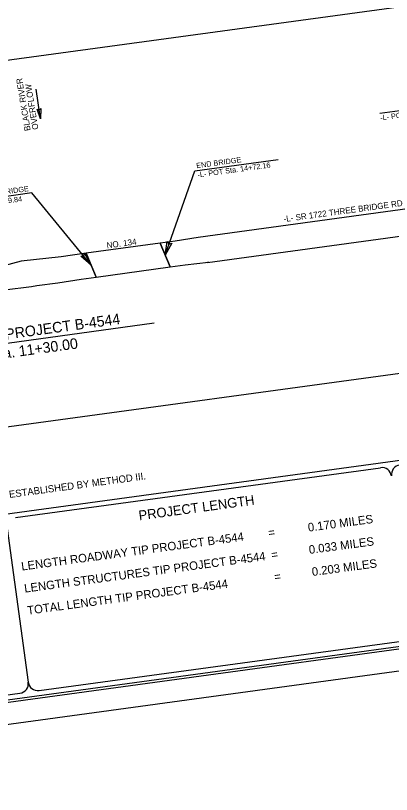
# Model space of a CAD drawing. Extents: x 2110583 to 2112764, y 580993 to 582575.
# Drawn here: x 2111407 to 2111873, y 580993 to 581957 of the extents above; entities that cross this region are included whole.
import ezdxf

# ---------------------------------------------------------------- set-up
doc = ezdxf.new("R2010")
doc.units = 0
for name, color, linetype in [('Default', 7, 'Continuous'), ('Prop DSN Text', 7, 'Continuous'), ('Prop Horizontal Alignment Station Label', 7, 'Continuous'), ('Prop Roadway Bridge', 7, 'Continuous'), ('Prop Shade Medium', 7, 'Continuous'), ('Prop Terminator CELL', 7, 'Continuous'), ('Sheet Data Field CELL', 7, 'Continuous'), ('Sheet Plot Border Inside CELL', 7, 'Continuous'), ('Sheet Plot Border Outside CELL', 7, 'Continuous'), ('Sheet Title CELL', 7, 'Continuous')]:
    doc.layers.add(name, color=color, linetype=linetype)

msp = doc.modelspace()

# ---------------------------------------------------------------- linework, layer by layer
at = {"layer": 'Default'}
msp.add_lwpolyline([(2111026.43, 581851.1), (2112527.69, 582055.98), (2112588.53, 581610.11), (2111087.27, 581405.24)], close=True, dxfattribs=at)
at = {"layer": 'Prop DSN Text'}
msp.add_line((2111437.98, 581828.89), (2111432.93, 581865.9), dxfattribs=at)
at = {"layer": 'Prop Horizontal Alignment Station Label'}
for p, q in [((2111962.26, 581849.66), (2111858.44, 581835.48)), ((2111629.48, 581764.81), (2111732.27, 581778.85)), ((2111592.36, 581660.37), (2111629.48, 581764.81)), ((2111427.45, 581737.24), (2111323.42, 581723.03)), ((2111500.89, 581647.89), (2111427.45, 581737.24)), ((2111579.06, 581576.04), (2111302.47, 581538.26))]:
    msp.add_line(p, q, dxfattribs=at)
at = {"layer": 'Prop Roadway Bridge'}
for p, q in [((2111586.18, 581675.09), (2111494.71, 581662.61)), ((2111598.54, 581645.66), (2111586.18, 581675.09)), ((2111494.71, 581662.61), (2111507.07, 581633.17)), ((2111507.07, 581633.17), (2111598.54, 581645.66))]:
    msp.add_line(p, q, dxfattribs=at)
at = {"layer": 'Prop Shade Medium'}
for p, q in [((2111994.42, 581731.39), (2111633.58, 581682.15)), ((2111644.95, 581651.4), (2111998.75, 581699.68)), ((2111604.76, 581677.63), (2111586.18, 581675.09)), ((2111586.18, 581675.09), (2111598.54, 581645.66)), ((2111633.58, 581682.15), (2111604.76, 581677.63)), ((2111463.75, 581658.38), (2111414.17, 581652.66)), ((2111494.71, 581662.61), (2111463.75, 581658.38)), ((2111507.07, 581633.17), (2111494.71, 581662.61)), ((2111414.17, 581652.66), (2111387.83, 581645.97)), ((2111598.54, 581645.66), (2111617.12, 581648.19)), ((2111617.12, 581648.19), (2111646.1, 581651.56)), ((2111646.1, 581651.56), (2111644.95, 581651.4)), ((2111459.66, 581626.12), (2111488.49, 581630.64)), ((2111488.49, 581630.64), (2111507.17, 581633.19)), ((2111433.71, 581622.58), (2111459.66, 581626.12))]:
    msp.add_line(p, q, dxfattribs=at)
msp.add_arc((2111114.87, 583958.95), 2358.03, 275.14998, 277.77101, dxfattribs=at)
at = {"layer": 'Prop Terminator CELL'}
for points in [[(2111438.43, 581841.67), (2111437.98, 581828.89), (2111434.05, 581841.15), (2111436.49, 581839.85)], [(2111600.6, 581675.04), (2111592.36, 581660.37), (2111595.17, 581677.07), (2111597.24, 581674.09)], [(2111492.57, 581662.51), (2111500.89, 581647.89), (2111488.02, 581658.9), (2111491.65, 581659.14)]]:
    msp.add_lwpolyline(points, close=True, dxfattribs=at)
at = {"layer": 'Sheet Plot Border Inside CELL'}
msp.add_lwpolyline([(2110773, 581021.72), (2112754.79, 581292.17), (2112583.51, 582547.28), (2110601.71, 582276.83)], close=True, dxfattribs=at)
at = {"layer": 'Sheet Plot Border Outside CELL'}
msp.add_lwpolyline([(2112585.22, 582574.72), (2110582.61, 582301.43), (2110761.18, 580992.92), (2112763.78, 581266.21)], close=True, dxfattribs=at)
at = {"layer": 'Sheet Title CELL'}
for p, q in [((2111002.17, 581286.33), (2112690.83, 581516.78)), ((2111407.31, 581335.54), (2111859.2, 581397.21)), ((2111397.04, 581322.04), (2111423.01, 581131.71))]:
    msp.add_line(p, q, dxfattribs=at)
for points in [[(2110967.61, 581051.37), (2112727.62, 581291.56)], [(2111436.53, 581121.42), (2111888.43, 581183.09)], [(2111240.31, 581094.66), (2111412.74, 581118.19)]]:
    msp.add_lwpolyline(points, dxfattribs=at)
for centre, major_axis, start_param, end_param in [((2111860.82, 581385.39), (-1.62, 11.9), 4.712389, 6.283185), ((2111884.61, 581388.63), (-1.62, 11.9), 0, 1.570796), ((2111411.12, 581130.14), (1.62, -11.9), 0, 1.570796), ((2111434.9, 581133.39), (1.62, -11.9), 4.712389, 6.283185)]:
    msp.add_ellipse(centre, major_axis=major_axis, ratio=0.999692, start_param=start_param, end_param=end_param, dxfattribs=at)

# ---------------------------------------------------------------- texts
at = {"layer": 'Prop DSN Text'}
for s, height, rotation, p in [('BLACK RIVER', 7.4721, 99.25807, (2111425.98, 581814.64)), ('OVERFLOW', 7.472, 99.25807, (2111435.65, 581816.22)), ('-L- SR 1722 THREE BRIDGE RD ', 7.4721, 7.77101, (2111739.6, 581701.16)), ('NO. 134', 7.472, 7.49037, (2111520.56, 581668.61)), ('CLEARING ON THIS PROJECT SHALL BE PERFORMED TO THE LIMITS ESTABLISHED BY METHOD III.', 8.8119, 7.77101, (2111004.72, 581305.86))]:
    msp.add_text(s, height=height, rotation=rotation, dxfattribs=at).set_placement(p)
at = {"layer": 'Prop Horizontal Alignment Station Label'}
for s, height, p in [('-L- POT Sta. 19+23.88', 6.5381, (2111859.24, 581826.86)), ('END BRIDGE', 6.538, (2111631.46, 581767.79)), ('-L- POT Sta. 14+72.16', 6.5381, (2111633.01, 581756.46)), ('BEGIN BRIDGE', 6.5381, (2111359.43, 581730.77)), ('-L- POT Sta. 13+79.84', 6.5381, (2111325.5, 581714.59)), ('BEGIN TIP PROJECT B-4544', 13.1191, (2111304.78, 581543.44)), ('-L- POC Sta. 11+30.00', 13.1191, (2111307.89, 581520.69))]:
    msp.add_text(s, height=height, rotation=7.77798, dxfattribs=at).set_placement(p)
at = {"layer": 'Sheet Data Field CELL'}
for s, height, p in [('0.170 MILES', 10.5053, (2111770, 581318.06)), ('=', 10.51, (2111720.92, 581311.41)), ('LENGTH ROADWAY TIP PROJECT B-4544', 10.5053, (2111415.07, 581269.9)), ('0.033 MILES', 10.5053, (2111771.19, 581290.43)), ('LENGTH STRUCTURES TIP PROJECT B-4544', 10.5053, (2111418.75, 581242.6)), ('=', 10.51, (2111724.61, 581284.12)), ('0.203 MILES', 10.5053, (2111774.88, 581263.13)), ('=', 10.51, (2111728.29, 581256.82)), ('TOTAL LENGTH TIP PROJECT B-4544', 10.5053, (2111422.44, 581215.31))]:
    msp.add_text(s, height=height, rotation=7.68602, dxfattribs=at).set_placement(p)
at = {"layer": 'Sheet Title CELL'}
msp.add_text('PROJECT LENGTH', height=12.0054, rotation=7.77101, dxfattribs=at).set_placement((2111560.54, 581332.05))

doc.saveas('drawing.dxf')
